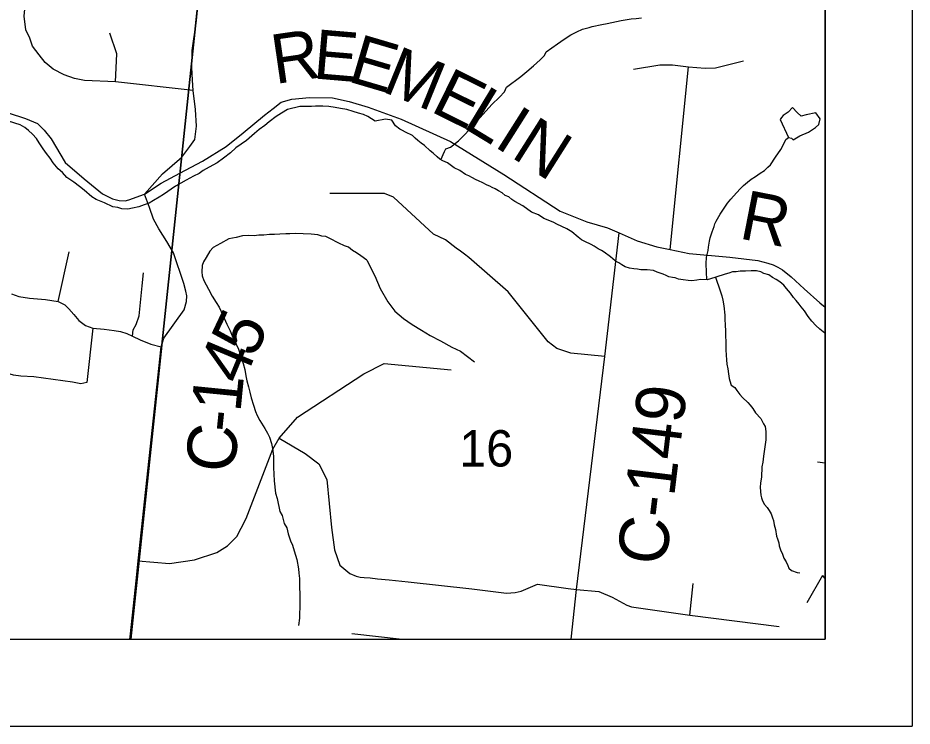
# Model space of a CAD drawing. Extents: x 0 to 34, y 0 to 22.
# Drawn here: x 7.97 to 9, y 14 to 14.815 of the extents above; entities that cross this region are included whole.
import ezdxf

# ---------------------------------------------------------------- set-up
doc = ezdxf.new("R2010")
doc.units = 0
for name, color, linetype in [('Default', 7, 'Continuous'), ('GM_X_County_Road', 7, 'Continuous'), ('GM_X_County_Road_Text', 7, 'Continuous'), ('GM_X_Minor_Lake', 7, 'Continuous'), ('GM_X_Minor_River', 7, 'Continuous'), ('GM_X_Section_Text', 7, 'Continuous'), ('GM_X_State_Route', 7, 'Continuous'), ('GM_X_Township_Road', 7, 'Continuous'), ('SH_Data', 7, 'Continuous')]:
    doc.layers.add(name, color=color, linetype=linetype)

msp = doc.modelspace()

# ---------------------------------------------------------------- linework, layer by layer
at = {"layer": 'Default'}
for points in [[(7.0916, 14.1), (8.0997, 14.1), (8.1869, 14.9268), (7.1496, 15.0512)], [(8.0997, 14.1), (8.9, 14.1), (8.9, 14.8387), (8.1869, 14.9268)]]:
    msp.add_lwpolyline(points, close=True, dxfattribs=at)
at = {"layer": 'GM_X_County_Road'}
for p, q in [((8.0991, 14.1029), (8.1063, 14.1708)), ((8.0988, 14.1), (8.0991, 14.1029))]:
    msp.add_line(p, q, dxfattribs=at)
for points in [[(8.1157, 14.6124), (8.1364, 14.6358), (8.1585, 14.655), (8.1676, 14.6673), (8.1736, 14.6753), (8.1756, 14.6907), (8.1741, 14.7099), (8.1717, 14.7317), (8.171, 14.7439), (8.17, 14.7584), (8.1706, 14.7781), (8.1753, 14.8125), (8.1812, 14.8706), (8.1985, 15.039), (8.2031, 15.0825)], [(7.918, 14.7192), (7.9784, 14.6998), (7.9923, 14.6937), (8, 14.6862), (8.008, 14.6764), (8.0242, 14.649), (8.0459, 14.63), (8.067, 14.613), (8.0785, 14.607), (8.0864, 14.6052), (8.0933, 14.605), (8.0975, 14.6058), (8.1157, 14.6124)], [(8.1157, 14.6124), (8.1349, 14.6253), (8.1562, 14.6367), (8.1822, 14.6505), (8.2098, 14.6673), (8.2292, 14.6833), (8.2538, 14.7036), (8.2638, 14.711), (8.2729, 14.7184), (8.2852, 14.7219), (8.3058, 14.7239), (8.3321, 14.7233), (8.3512, 14.7193), (8.3732, 14.7127), (8.4114, 14.699), (8.468, 14.6733), (8.5297, 14.635), (8.5943, 14.5929), (8.6251, 14.5805), (8.649, 14.5739), (8.6623, 14.5681), (8.683, 14.5589), (8.7057, 14.5518), (8.7213, 14.5487), (8.743, 14.5441), (8.7898, 14.5398), (8.8224, 14.5362), (8.8338, 14.5332), (8.84, 14.5311), (8.8451, 14.5284), (8.8507, 14.5254), (8.8608, 14.5172), (8.8755, 14.5035), (8.8935, 14.4873), (8.9, 14.4825)], [(8.1063, 14.1708), (8.1084, 14.1902), (8.1346, 14.4369), (8.1378, 14.4468), (8.1613, 14.4794), (8.1639, 14.4888), (8.1642, 14.4955), (8.1633, 14.501), (8.1608, 14.5098), (8.1488, 14.5448), (8.1412, 14.558), (8.132, 14.5724), (8.126, 14.5836), (8.1211, 14.5972), (8.1157, 14.6124)], [(8.6071, 14.1), (8.6133, 14.1574), (8.6459, 14.4254), (8.6623, 14.5681)]]:
    msp.add_lwpolyline(points, dxfattribs=at)
at = {"layer": 'GM_X_Minor_Lake'}
msp.add_line((8.8969, 14.1735), (8.9, 14.1691), dxfattribs=at)
for points in [[(8.8543, 14.6754), (8.8576, 14.6776), (8.861, 14.6768), (8.8628, 14.6752), (8.8705, 14.6796), (8.8805, 14.6839), (8.8886, 14.6894), (8.8925, 14.6928), (8.8941, 14.6992), (8.889, 14.7062), (8.8779, 14.7037), (8.8722, 14.7023), (8.8677, 14.7066), (8.8622, 14.7124), (8.8571, 14.7069), (8.8513, 14.7032)], [(8.8513, 14.7032), (8.8494, 14.7007), (8.8481, 14.6984), (8.8576, 14.6776)], [(8.8969, 14.1735), (8.8788, 14.142)]]:
    msp.add_lwpolyline(points, dxfattribs=at)
at = {"layer": 'GM_X_Minor_River'}
for points in [[(8.4568, 14.6522), (8.4611, 14.6617), (8.4627, 14.6647), (8.4681, 14.6668), (8.4774, 14.6738), (8.4852, 14.6819), (8.495, 14.6927), (8.5056, 14.7046), (8.5158, 14.7157), (8.5244, 14.7242), (8.5303, 14.7302), (8.5327, 14.7358), (8.549, 14.7479), (8.556, 14.7538), (8.5638, 14.7604), (8.5716, 14.7671), (8.5763, 14.7723), (8.5783, 14.7764), (8.5915, 14.7856), (8.5992, 14.791), (8.6066, 14.7958), (8.6135, 14.7994), (8.6201, 14.8026), (8.6277, 14.8043), (8.6312, 14.8054), (8.6426, 14.8077), (8.6488, 14.8091), (8.6541, 14.8101), (8.6595, 14.8114), (8.6648, 14.8124), (8.6763, 14.8144), (8.682, 14.8146), (8.6881, 14.8156)], [(8.3813, 14.6966), (8.3727, 14.7019), (8.3679, 14.7043), (8.3622, 14.7056), (8.3559, 14.7078), (8.3487, 14.7099), (8.3412, 14.7113), (8.3351, 14.7123), (8.3279, 14.7133), (8.3211, 14.7139), (8.3124, 14.7138), (8.3078, 14.7136), (8.2991, 14.7135), (8.2945, 14.7133), (8.29, 14.7123), (8.285, 14.7113), (8.2804, 14.71), (8.2734, 14.7057), (8.2672, 14.7021), (8.259, 14.6959), (8.2543, 14.6915), (8.2477, 14.6868), (8.2422, 14.6824), (8.2332, 14.6744), (8.2208, 14.6657), (8.2145, 14.6602), (8.2067, 14.654), (8.1993, 14.6486), (8.19, 14.6436), (8.183, 14.6396), (8.1784, 14.6364), (8.1718, 14.6332), (8.1637, 14.6285), (8.1575, 14.6253), (8.1513, 14.6217), (8.1373, 14.612), (8.1323, 14.6091), (8.1257, 14.6052), (8.121, 14.6023), (8.1152, 14.6002), (8.1091, 14.5981), (8.1018, 14.5965), (8.0965, 14.5951), (8.0893, 14.5958), (8.0848, 14.5971), (8.0791, 14.598), (8.0694, 14.6025), (8.06, 14.6063), (8.0548, 14.6095), (8.046, 14.617), (8.0408, 14.6214), (8.0341, 14.6262), (8.026, 14.6318), (8.0212, 14.6376), (8.0161, 14.6416), (8.0102, 14.6487), (8.007, 14.6541), (8.0026, 14.6592), (7.9986, 14.6646), (7.9943, 14.6716), (7.9911, 14.6767), (7.9863, 14.6814), (7.9819, 14.6857), (7.9775, 14.6893), (7.9722, 14.6922), (7.9587, 14.6964)], [(8.8145, 14.5242), (8.808, 14.524), (8.8019, 14.5238), (8.7973, 14.5232), (8.7932, 14.5229), (8.7889, 14.5215), (8.7847, 14.5205), (8.774, 14.517), (8.7675, 14.5149), (8.764, 14.5138), (8.756, 14.5141), (8.7518, 14.5134), (8.7461, 14.5128), (8.7419, 14.5129), (8.7363, 14.5138), (8.731, 14.5148), (8.7268, 14.516), (8.7238, 14.5165), (8.7196, 14.5174), (8.7166, 14.519), (8.7132, 14.5202), (8.7095, 14.5215), (8.7061, 14.5227), (8.7019, 14.5247), (8.6947, 14.5253), (8.6875, 14.5255), (8.6837, 14.526), (8.6795, 14.5265), (8.6742, 14.5274), (8.6693, 14.529), (8.6656, 14.5311), (8.6619, 14.5334), (8.6577, 14.5358), (8.6525, 14.5402), (8.6451, 14.5457), (8.6421, 14.5477), (8.6383, 14.5497), (8.6335, 14.5525), (8.6301, 14.5545), (8.623, 14.5581), (8.6192, 14.5601), (8.6151, 14.5629), (8.6081, 14.5692), (8.6021, 14.5724), (8.5908, 14.5781), (8.5871, 14.5797), (8.5788, 14.5834), (8.5758, 14.5846), (8.5694, 14.5886), (8.5615, 14.5918), (8.5514, 14.599), (8.5421, 14.6042), (8.5387, 14.6062), (8.5354, 14.6093), (8.5312, 14.611), (8.5275, 14.6141), (8.5234, 14.6165), (8.5197, 14.6185), (8.5163, 14.6201), (8.5133, 14.6217), (8.5103, 14.623), (8.5046, 14.6258), (8.5013, 14.6274), (8.4971, 14.6294), (8.4934, 14.6314), (8.4893, 14.6335), (8.4855, 14.6351), (8.4788, 14.6398), (8.4724, 14.6427), (8.4646, 14.6486), (8.4593, 14.6507), (8.4559, 14.6527), (8.4526, 14.6554), (8.4481, 14.6597), (8.4448, 14.6625), (8.4381, 14.6684), (8.4344, 14.6712), (8.4306, 14.6743), (8.4273, 14.6771), (8.4243, 14.6802), (8.4161, 14.6839), (8.4127, 14.6859), (8.4097, 14.6875), (8.4049, 14.691), (8.4004, 14.6977), (8.3933, 14.699), (8.3813, 14.6966)], [(8.7635, 14.5138), (8.7626, 14.5322), (8.7632, 14.5401), (8.7649, 14.5477), (8.7654, 14.5515), (8.7664, 14.5583), (8.7672, 14.5621), (8.7697, 14.5693), (8.7721, 14.5753), (8.7726, 14.5783), (8.7742, 14.5813), (8.779, 14.5896), (8.7841, 14.5974), (8.7873, 14.6023), (8.7912, 14.6067), (8.794, 14.6101), (8.7979, 14.6145), (8.8018, 14.6186), (8.8057, 14.6223), (8.8104, 14.6264), (8.8147, 14.6297), (8.8197, 14.633), (8.8251, 14.6366), (8.8298, 14.6399), (8.8337, 14.6436), (8.8368, 14.6462), (8.8424, 14.6552), (8.8487, 14.6641), (8.8507, 14.6675), (8.8543, 14.6754)], [(8.3716, 14.5366), (8.3646, 14.5414), (8.3597, 14.545), (8.3553, 14.5478), (8.3505, 14.5514), (8.346, 14.5531), (8.3396, 14.5559), (8.3292, 14.5616), (8.3243, 14.5637), (8.3198, 14.5642), (8.3153, 14.5655), (8.3077, 14.5665), (8.2891, 14.5672), (8.2831, 14.567), (8.2785, 14.5668), (8.2713, 14.5663), (8.2652, 14.5661), (8.2595, 14.5659), (8.253, 14.5654), (8.2473, 14.5652), (8.242, 14.5646), (8.2351, 14.5649), (8.2283, 14.5644), (8.221, 14.5627), (8.2126, 14.5611), (8.2029, 14.5557), (8.1948, 14.5511), (8.1909, 14.5467), (8.1864, 14.5396), (8.1836, 14.5347), (8.1819, 14.5302), (8.1817, 14.523), (8.1819, 14.5185), (8.184, 14.5131), (8.1865, 14.508), (8.1894, 14.503), (8.1936, 14.4949), (8.1979, 14.4879), (8.2016, 14.4824), (8.2058, 14.4732), (8.2104, 14.4628), (8.2143, 14.455), (8.2167, 14.4492), (8.2213, 14.4396), (8.2238, 14.4342), (8.2266, 14.4261), (8.2293, 14.4176), (8.231, 14.4107), (8.2322, 14.4035), (8.2336, 14.3977), (8.2352, 14.3908), (8.2369, 14.3847), (8.2386, 14.3778), (8.241, 14.3697), (8.2434, 14.3624), (8.2455, 14.3578), (8.2483, 14.352), (8.2541, 14.3427), (8.2573, 14.3373), (8.2594, 14.3326), (8.2618, 14.3253), (8.2631, 14.3196), (8.264, 14.3108), (8.2641, 14.3032), (8.2643, 14.2979), (8.2649, 14.2826), (8.2663, 14.2682), (8.2684, 14.262), (8.2713, 14.2471), (8.2741, 14.2424), (8.2765, 14.2332), (8.2794, 14.2282), (8.281, 14.2213), (8.2838, 14.2132), (8.2859, 14.2082), (8.2879, 14.2017), (8.291, 14.192), (8.2929, 14.181), (8.2935, 14.176), (8.294, 14.1699), (8.2942, 14.1619), (8.2945, 14.1501), (8.2946, 14.1418), (8.294, 14.1243), (8.2931, 14.1157)], [(8.3716, 14.5366), (8.3809, 14.5184), (8.387, 14.5038), (8.3958, 14.4887), (8.4039, 14.4779), (8.4139, 14.4693), (8.424, 14.4626), (8.4345, 14.4559), (8.4446, 14.4499), (8.4566, 14.4435), (8.4698, 14.4364), (8.4795, 14.4316), (8.4956, 14.4194)], [(8.9, 14.4524), (8.8996, 14.4525), (8.8937, 14.4569), (8.8892, 14.4612), (8.8844, 14.4663), (8.8804, 14.4717), (8.876, 14.478), (8.8723, 14.4826), (8.8697, 14.4857), (8.8664, 14.49), (8.8635, 14.4935), (8.8598, 14.4986), (8.8554, 14.504), (8.8521, 14.5076), (8.8476, 14.5115), (8.8435, 14.5143), (8.839, 14.5167), (8.8349, 14.5195), (8.8292, 14.5211), (8.8255, 14.5232), (8.8206, 14.5241), (8.8145, 14.5242)], [(8.7736, 14.5168), (8.7789, 14.5012), (8.7806, 14.4955), (8.782, 14.4905), (8.783, 14.484), (8.7842, 14.4733), (8.7841, 14.4702), (8.7846, 14.46), (8.7849, 14.4565), (8.7848, 14.452), (8.7852, 14.4398), (8.7854, 14.4333), (8.7856, 14.4272), (8.7862, 14.4218), (8.7865, 14.4169), (8.7875, 14.4115), (8.7885, 14.4058), (8.7891, 14.4004), (8.7898, 14.3974), (8.7915, 14.3927), (8.7957, 14.39), (8.7982, 14.3865), (8.8015, 14.3818), (8.8045, 14.3783), (8.8108, 14.3728), (8.8134, 14.3697), (8.8163, 14.3658), (8.8196, 14.3607), (8.8255, 14.3541), (8.8287, 14.3479), (8.8306, 14.3448), (8.8315, 14.3391), (8.8313, 14.3296), (8.8289, 14.311), (8.8279, 14.3041), (8.827, 14.2985), (8.8263, 14.2867), (8.8254, 14.2802), (8.8249, 14.2749), (8.8258, 14.2661), (8.8264, 14.2627), (8.8275, 14.2592), (8.83, 14.255), (8.833, 14.2518), (8.8352, 14.2483), (8.8374, 14.2445), (8.8391, 14.2399), (8.8402, 14.2368), (8.8412, 14.2318), (8.8426, 14.2264), (8.8439, 14.2188), (8.8449, 14.2157), (8.8463, 14.2111), (8.847, 14.2076), (8.8484, 14.203), (8.8505, 14.198), (8.8523, 14.1934), (8.8549, 14.1892), (8.8567, 14.1849), (8.8581, 14.1818), (8.8611, 14.1791), (8.8675, 14.177), (8.8705, 14.1765)]]:
    msp.add_lwpolyline(points, dxfattribs=at)
at = {"layer": 'GM_X_State_Route'}
msp.add_lwpolyline([(5.2499, 15.926), (5.1715, 15.1469), (5.1456, 14.8898), (5.1035, 14.4713), (5.0661, 14.1), (8.9, 14.1), (8.9, 16.8616)], dxfattribs=at)
at = {"layer": 'GM_X_Township_Road'}
for p, q in [((8.7213, 14.5487), (8.7423, 14.7591)), ((8.0162, 14.489), (8.0287, 14.5461)), ((8.9, 14.3026), (8.891, 14.3038)), ((8.7437, 14.1277), (8.7477, 14.1641)), ((8.3546, 14.1067), (8.4126, 14.1))]:
    msp.add_line(p, q, dxfattribs=at)
for points in [[(8.1717, 14.7317), (8.0821, 14.7417), (8.0463, 14.7433), (8.0348, 14.7457), (8.023, 14.7499), (8.0101, 14.7565), (8.0012, 14.764), (7.9942, 14.7728), (7.9863, 14.783), (7.9832, 14.7921), (7.9789, 14.8016), (7.9768, 14.8175), (7.9835, 14.8835), (7.9847, 14.8869), (7.9869, 14.8894), (7.9899, 14.8902), (7.9943, 14.8903), (8.0095, 14.8899), (8.0235, 14.8899), (8.046, 14.8906), (8.0757, 14.8894), (8.0947, 14.887), (8.1171, 14.8827), (8.1812, 14.8706)], [(8.0821, 14.7417), (8.0835, 14.774), (8.0756, 14.7978)], [(8.6788, 14.7563), (8.7094, 14.7616), (8.7239, 14.7616), (8.7423, 14.7591), (8.7616, 14.7575), (8.7734, 14.7579), (8.8056, 14.766)], [(8.4842, 14.5436), (8.4796, 14.5469), (8.4748, 14.5505), (8.4623, 14.5601), (8.4485, 14.5665), (8.4024, 14.6091), (8.3919, 14.6132), (8.3291, 14.6134)], [(8.6459, 14.4254), (8.6067, 14.4295), (8.5908, 14.4349), (8.5808, 14.4423), (8.5345, 14.5), (8.4894, 14.5397), (8.4842, 14.5436)], [(8.1016, 14.4491), (8.1023, 14.4562), (8.1061, 14.4626), (8.1095, 14.4725), (8.1129, 14.5068), (8.1143, 14.5218)], [(7.9622, 14.4978), (7.9709, 14.4945), (7.9829, 14.4927), (8.0015, 14.4912), (8.0162, 14.489), (8.0238, 14.4849), (8.0285, 14.4804), (8.0339, 14.4741), (8.0397, 14.4669), (8.0474, 14.4612), (8.056, 14.4581), (8.0691, 14.4569), (8.0806, 14.4557), (8.0878, 14.4542), (8.0952, 14.4522), (8.1016, 14.4491), (8.1106, 14.4446), (8.123, 14.4398), (8.1346, 14.4369)], [(8.056, 14.4581), (8.0492, 14.3956), (8.042, 14.3942), (8.0325, 14.3962), (7.9881, 14.402), (7.9732, 14.4029), (7.9645, 14.4041), (7.9558, 14.4068), (7.9441, 14.4095), (7.9342, 14.4134), (7.9234, 14.4167), (7.9117, 14.4185), (7.8961, 14.4206), (7.8356, 14.4296)], [(8.1084, 14.1902), (8.1445, 14.1874), (8.173, 14.1914), (8.1987, 14.1998), (8.211, 14.2076), (8.2218, 14.2184), (8.2269, 14.228), (8.2325, 14.2391), (8.2633, 14.3188), (8.2707, 14.3316), (8.2917, 14.3557), (8.3684, 14.4055), (8.3918, 14.4175), (8.4688, 14.4102)], [(8.2707, 14.3316), (8.3007, 14.3138), (8.3162, 14.3021), (8.3255, 14.2841), (8.3309, 14.2286), (8.3345, 14.2031), (8.3405, 14.1852), (8.3429, 14.1832)], [(8.3429, 14.1832), (8.3522, 14.1756), (8.3593, 14.1726), (8.3639, 14.1714), (8.3688, 14.1711), (8.3754, 14.1708), (8.3841, 14.1694), (8.3975, 14.1684), (8.4194, 14.1661), (8.4928, 14.1579), (8.5325, 14.1532), (8.5427, 14.1537), (8.5495, 14.1552), (8.5685, 14.1634), (8.6037, 14.1583), (8.6133, 14.1574), (8.6391, 14.1549), (8.6545, 14.1483), (8.6714, 14.1393), (8.6767, 14.1373), (8.7437, 14.1277), (8.847, 14.1146)]]:
    msp.add_lwpolyline(points, dxfattribs=at)
at = {"layer": 'SH_Data'}
for p, q in [((9, 21), (9, 14)), ((8.9, 20.9), (8.9, 14.1)), ((2.1, 14.1), (8.9, 14.1)), ((2, 14), (9, 14))]:
    msp.add_line(p, q, dxfattribs=at)

# ---------------------------------------------------------------- texts
at = {"layer": 'GM_X_County_Road_Text'}
for s, height, rotation, p in [('R', 0.0568, 8.2678, (8.266, 14.7392)), ('E', 0.0568, 355.1299, (8.3088, 14.7459)), ('E', 0.0568, 343.5987, (8.3482, 14.7428)), ('M', 0.0568, 337.8753, (8.3875, 14.7313)), ('E', 0.0568, 333.6017, (8.4436, 14.7085)), ('L', 0.0568, 328.7586, (8.4806, 14.6902)), ('I', 0.0568, 327.6274, (8.5167, 14.6684)), ('N', 0.0568, 327.6509, (8.5364, 14.6559)), ('R', 0.0568, 348.9725, (8.7993, 14.5618)), ('5', 0.0568, 64.672, (8.2416, 14.4224)), ('4', 0.0568, 67.3489, (8.2284, 14.3908)), ('1', 0.0568, 84.3611, (8.226, 14.3603)), ('C-149', 0.05682, 83.0806, (8.7161, 14.1836)), ('-', 0.0568, 84.1355, (8.2236, 14.3368)), ('C', 0.0568, 84.0873, (8.2188, 14.2903))]:
    msp.add_text(s, height=height, rotation=rotation, dxfattribs=at).set_placement(p)
at = {"layer": 'GM_X_Section_Text'}
msp.add_text('16', height=0.04186, rotation=0, dxfattribs=at).set_placement((8.4781, 14.2989))

doc.saveas('drawing.dxf')
